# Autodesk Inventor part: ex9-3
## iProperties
Shininess: 64.0
Length Units: 11272
Angle Units: 11279
Time Units: 11290
Mass Units: 11286
Length Display Precision: 3
Angle Display Precision: 2
Compacted: True
Part Number: ex9-3
Document SubType Name: Sheet Metal
Created: 2002-11
Designer: Elise Moss
Density: 0.0
Volumn: 0.0
Area: 0.0
PropertySet Name: Model Information
Control State: 0
Master: False
Checked Out: False
Author: Elise Moss
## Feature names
1. Plate1
2. Bend1
3. Plate2
4. Bend2
5. Cut1
